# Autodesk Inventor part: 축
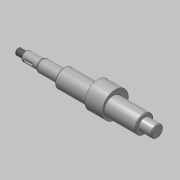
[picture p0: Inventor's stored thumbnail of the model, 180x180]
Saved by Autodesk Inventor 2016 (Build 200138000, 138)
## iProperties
Created: 2015-12
Part Number: 축
Document SubType Name: Modeling
Designer: mdu
Density: 7.86 g/cm^3
Material: 강철, 연강
Appearance: 강철
Mass: 489.93 g
Surface Area: 127.025 cm^2
Volume: 62.3321 cm^3
Author: mdu
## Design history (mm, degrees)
sketch "스케치1"
  geometry: L1 (62, 100.9)-(62, 67.1) reference; L2 (51, 101.2)-(51, 84) reference; L3 (-51, 84)-(-51, 101.2) reference; L4 (-62, 67.1)-(-62, 100.9) reference; L5 (-51.6, 91.5)-(-61.4, 91.5) reference; L6 (51.6, 91.5)-(61.4, 91.5) reference; L7 (67, 84)-(-109, 84); L8 (-77, 64.201)-(-77, 103.799) reference; L9 (67, 84)-(67, 91.5); L10 (67, 91.5)-(51, 91.5); L11 (51, 91.5)-(51, 95.5); L12 (51, 95.5)-(-51, 95.5); L13 (-51, 95.5)-(-51, 91.5); L14 (-51, 91.5)-(-79, 91.5); L15 (-79, 91.5)-(-79, 90); L16 (-79, 90)-(-99, 90); L17 (-99, 90)-(-99, 88); L18 (-99, 88)-(-109, 88); L19 (-109, 88)-(-109, 84); 2 further points
  constraints: 28 end point, 7 parallel, 5 point on line, 4 perpendicular, 2 collinear, 2 horizontal, 1 midpoint, 4 other
  dimensions: "d0" = 5 distance from line of L7.start L1; "d2" = 2 distance between parallel lines of L15 L8; "d3" = 23 diameter of L12 L7; "d4" = 12 diameter of L16 L7; "d7" = 20 distance of L15.end L16.end; "d8" = 10 distance between parallel lines of L17 L19; "d9" = 8 diameter of L18 L7
revolve "회전1" sketch "스케치1" stored, may be unused: angle "d10" = 90 deg
sketch "스케치2"
  geometry: C1 r 11.5 at (84, 0) reference; C2 r 11.5 at (84, 0) reference; C3 r 16.5 at (87, 0); 1 further point
  constraints: 1 centre point, 1 horizontal alignment
  dimensions: "d11" = 33 diameter of C3; "d12" = 3 distance of C3.centre C1.centre
extrude "돌출1" join sketch "스케치2" stored distance "d13" = 22; taper "d14" = 0 deg
chamfer "모따기1" distance "d15" = 1; stored, may be unused: second distance "d16" = 2, angle "d17" = 45 deg
feature "스레드1" dims "d18" = 8, "d19" = 0
node "작업 평면1"
sketch "스케치3"
  geometry: L1 (-5, -2)-(3, -2); L2 (3, 2)-(-5, 2); L3 (-10, -5)-(-10, 5) reference; A1 r 2 centre (3, 0) between (3, -2) and (3, 2); A2 r 2 centre (-5, 0) between (-5, 2) and (-5, -2); 2 further points
  constraints: 4 end point, 4 point on circle, 4 tangent, 2 centre point, 1 horizontal, 1 horizontal alignment, 1 midpoint, 1 parallel
  dimensions: "d20" = 4 distance between parallel lines of L1 L2; "d21" = 12 dimension on A1 A2; "d22" = 3 distance edge to line of A2 L3
extrude "돌출2" cut sketch "스케치3" distance "d23" = 2.5; taper "d24" = 0 deg
fillet "모깎기1" dims "d25" = 0.3
chamfer "모따기2" distance "d27" = 1.65; stored, may be unused: second distance "d28" = 2, angle "d29" = 30 deg
fillet "모깎기3" dims "d30" = 2
node "솔리드1"
node "참조1"
node "참조2"
node "참조3"
node "참조4"
node "참조5"
node "투영된 루프1"
